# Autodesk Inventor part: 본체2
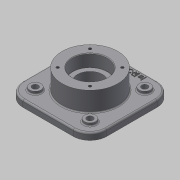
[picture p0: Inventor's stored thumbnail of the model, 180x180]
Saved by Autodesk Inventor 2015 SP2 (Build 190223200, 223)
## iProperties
Created: 2015-07
Part Number: 본체2
Material: 일반
Document SubType Name: Modeling
Designer: AMC
Density: 1 g/cm^3
Appearance: 기본값
Author: AMC
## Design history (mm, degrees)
sketch "스케치1"
  geometry: L1 (-75, -75)-(75, -75); L2 (75, -75)-(75, 75); L3 (75, 75)-(-75, 75); L4 (-75, 75)-(-75, -75); L5 (-75, -75)-(75, 75); L6 (75, -75)-(-75, 75); 1 further point
  constraints: 12 end point, 2 midpoint, 2 parallel, 1 horizontal, 1 perpendicular
  dimensions: "d0" = 150 distance of L3.end L2.end; "d1" = 150 distance of L2.end L1.end
extrude "돌출1" new body sketch "스케치1" distance "d2" = 12; taper "d3" = 0 deg
sketch "스케치2"
  geometry: C1 r 50 at (0, 0); 1 further point
  constraints: 1 centre point, 1 coincident
  dimensions: "d4" = 100 diameter of C1
extrude "돌출2" join sketch "스케치2" stored distance "d5" = 70; taper "d6" = 0 deg
hole "구멍1" diameter "d9" = 45; stored, may be unused: countersink angle "d13" = 90 deg, drill point angle "d15" = 0 deg; dims "d10" = 6, "d11" = 62, "d12" = 22, "d14" = 35, "d132" = 10, "d133" = 10
hole "구멍2" diameter "d18" = 45; stored, may be unused: countersink angle "d22" = 90 deg, drill point angle "d24" = 0 deg; dims "d19" = 6, "d20" = 62, "d21" = 22, "d23" = 35, "d134" = 10, "d135" = 10
sketch "스케치3"
  geometry: L1 (0, 0)-(41, 0); L2 (0, 0)-(28.991, -28.991); A1 r 41 centre (0, 0) between (41, 0) and (28.991, -28.991); 1 further point
  constraints: 4 end point, 2 point on circle, 1 centre point, 1 coincident, 1 horizontal
  dimensions: "d25" = 82 diameter of A1; "d26" = 45 deg angle of L2 L1
hole "구멍3" sketch "스케치3" at (28.991, -28.991) diameter "d27" = 4.917; stored, may be unused: countersink angle "d31" = 90 deg, drill point angle "d33" = 118 deg; dims "d28" = 10, "d29" = 52, "d30" = 22, "d32" = 13
sketch "스케치4"
  geometry: L1 (0, 0)-(41, 0); L2 (0, 0)-(28.991, -28.991); A1 r 41 centre (0, 0) between (41, 0) and (28.991, -28.991); 1 further point
  constraints: 4 end point, 2 point on circle, 1 centre point, 1 coincident, 1 horizontal
  dimensions: "d37" = 82 diameter of A1; "d38" = 45 deg angle of L2 L1
hole "구멍4" sketch "스케치4" at (28.991, -28.991) diameter "d39" = 4.917; stored, may be unused: countersink angle "d43" = 90 deg, drill point angle "d45" = 118 deg; dims "d40" = 10, "d41" = 52, "d42" = 22, "d44" = 13
sketch "스케치6"
  geometry: L1 (75, 75)-(-75, 75) reference; L2 (-75, 75)-(-75, -75) reference; L3 (-75, -75)-(75, -75) reference; L4 (75, -75)-(75, 75) reference; C1 r 10 at (-49, 49); C2 r 10 at (49, 49); C3 r 10 at (49, -49); C4 r 10 at (-49, -49); 1 further point
  constraints: 4 centre point
  dimensions: "d72" = 20 diameter of C1; "d73" = 20 diameter of C2; "d74" = 20 diameter of C3; "d75" = 20 diameter of C4; "d76" = 26 distance from line of C1.centre L1; "d77" = 26 distance from line of L2 C1.centre; "d78" = 26 distance from line of C4.centre L2; "d79" = 26 distance from line of L3 C4.centre; "d80" = 26 distance from line of L4 C3.centre; "d81" = 26 distance from line of L3 C3.centre; "d82" = 26 distance from line of C2.centre L1; "d83" = 26 distance from line of C2.centre L4
extrude "돌출4" join sketch "스케치6" distance "d84" = 5; taper "d85" = 0 deg
hole "구멍6" diameter "d88" = 11; stored, may be unused: countersink angle "d92" = 90 deg, drill point angle "d94" = 0 deg; dims "d86" = 10, "d87" = 10, "d89" = 10, "d90" = 52, "d91" = 22, "d93" = 50
hole "구멍7" diameter "d97" = 11; stored, may be unused: countersink angle "d101" = 90 deg, drill point angle "d103" = 0 deg; dims "d95" = 10, "d96" = 10, "d98" = 10, "d99" = 52, "d100" = 22, "d102" = 50
hole "구멍8" diameter "d106" = 11; stored, may be unused: countersink angle "d110" = 90 deg, drill point angle "d112" = 0 deg; dims "d104" = 10, "d105" = 10, "d107" = 10, "d108" = 52, "d109" = 22, "d111" = 50
hole "구멍9" diameter "d115" = 11; stored, may be unused: countersink angle "d119" = 90 deg, drill point angle "d121" = 0 deg; dims "d113" = 10, "d114" = 10, "d116" = 10, "d117" = 52, "d118" = 22, "d120" = 50
fillet "모깎기1" dims "d122" = 2
fillet "모깎기2" dims "d123" = 30
fillet "모깎기4" dims "d125" = 0.3
chamfer "모따기1" distance "d126" = 1; stored, may be unused: second distance "d127" = 2, angle "d128" = 45 deg
sketch "스케치7"
  geometry: 2 further points
  constraints: 1 vertical alignment, 1 other
  dimensions: "d129" = 65 distance of point (0, 0) point (0, 65)
fillet "모깎기5" dims "d130" = 3
fillet "모깎기6" dims "d131" = 3
feature "엠보싱1" dims "d0" = 150, "d1" = 150, "d136" = 1, "d137" = 0
node "솔리드1"
pattern_circular "원형 패턴1" dims angle "d35" = 360 deg
pattern_circular "원형 패턴2" dims angle "d47" = 360 deg
